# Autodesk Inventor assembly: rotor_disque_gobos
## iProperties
Created: 2011-01
Part Number: rotor_disque_gobos
Document SubType Name: Assembly
Designer: eric
Mass: 12.0826 g
Surface Area: 201.089 cm^2
Volume: 12.0826 cm^3
Density: 1 g/cm^3
Norme de conversion: IGES 5.3
Nom du fichier: No Iges File Name specified
Préprocesseur: Autodesk Inventor 2011
Postprocesseur: Build: 342, Release: 2008 SP3 - Date: Tue 05/27/2008
Unités envoyées: MM
Incertitude: 0.01
Author: eric
